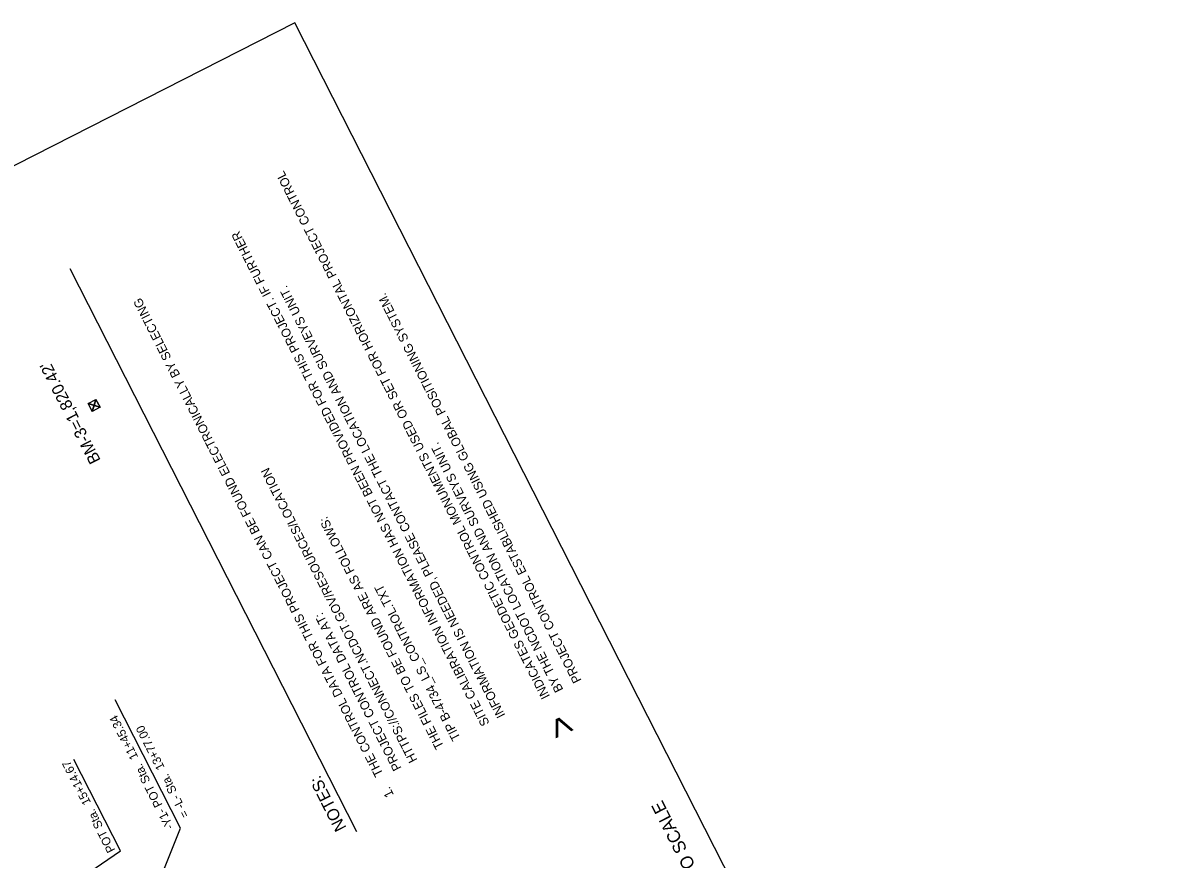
# Model space of a CAD drawing. Extents: x 558500 to 560321, y 514546 to 516470.
# Drawn here: x 559286 to 560218, y 515787 to 516470 of the extents above; entities that cross this region are included whole.
import ezdxf

# ---------------------------------------------------------------- set-up
doc = ezdxf.new("R2010")
doc.units = 0
for name, color, linetype in [('CTL Bench Mark CELL', 7, 'Continuous'), ('CTL Sheet Border CELL', 7, 'Continuous'), ('CTL Sheet Notes CELL', 7, 'Continuous'), ('CTL Supplemental Horizontal and Vertical Text', 7, 'Continuous'), ('Prop Horizontal Alignment Station Label', 7, 'Continuous')]:
    doc.layers.add(name, color=color, linetype=linetype)

msp = doc.modelspace()

# ---------------------------------------------------------------- linework, layer by layer
at = {"layer": 'CTL Bench Mark CELL'}
msp.add_line((559344.09, 516157.75), (559344.09, 516157.75), dxfattribs=at)
msp.add_lwpolyline([(559345.57, 516162.62), (559348.94, 516156.27), (559342.59, 516152.9), (559339.22, 516159.25)], close=True, dxfattribs=at)
for points in [[(559348.94, 516156.27), (559339.22, 516159.25), (559344.08, 516157.76), (559342.59, 516152.9), (559345.57, 516162.62)], [(559344.08, 516157.76), (559339.22, 516159.25), (559342.59, 516152.9), (559344.08, 516157.76)], [(559344.08, 516157.76), (559348.94, 516156.27), (559345.57, 516162.62), (559344.08, 516157.76)]]:
    msp.add_lwpolyline(points, dxfattribs=at)
at = {"layer": 'CTL Sheet Border CELL'}
for p, q in [((559508.09, 516470.33), (558531.71, 515973.23)), ((560218.25, 515075.49), (559508.09, 516470.33))]:
    msp.add_line(p, q, dxfattribs=at)
at = {"layer": 'CTL Sheet Notes CELL'}
msp.add_line((559558.64, 515809.53), (559324.68, 516269.42), dxfattribs=at)
at = {"layer": 'Prop Horizontal Alignment Station Label'}
for p, q in [((559414.66, 515812.44), (559361.24, 515917.36)), ((559365.63, 515793.86), (559327.55, 515868.65)), ((559365.53, 515689.77), (559414.66, 515812.44)), ((559265.98, 515725.85), (559365.63, 515793.86))]:
    msp.add_line(p, q, dxfattribs=at)

# ---------------------------------------------------------------- texts
at = {"layer": 'CTL Sheet Border CELL'}
msp.add_text('NOTE: DRAWING NOT TO SCALE', height=10.4348, rotation=116.87668, dxfattribs=at).set_placement((559907.7, 515639.52))
at = {"layer": 'CTL Sheet Notes CELL'}
for s, height, rotation, p in [('INDICATES GEODETIC CONTROL MONUMENTS USED OR SET FOR HORIZONTAL PROJECT CONTROL', 7.337, 116.85803, (559716.63, 515920.14)), ('SITE CALIBRATION INFORMATION HAS NOT BEEN PROVIDED FOR THIS PROJECT. IF FURTHER', 7.337, 116.96328, (559667.33, 515898.11)), ('INFORMATION IS NEEDED, PLEASE CONTACT THE LOCATION AND SURVEYS UNIT.', 7.337, 116.96328, (559680.21, 515904.66)), ('PROJECT CONTROL ESTABLISHED USING GLOBAL POSITIONING SYSTEM.', 7.337, 116.85803, (559742.41, 515933.19)), ('1.    THE CONTROL DATA FOR THIS PROJECT CAN BE FOUND ELECTRONICALLY BY SELECTING', 7.337, 116.96328, (559589.14, 515839.68)), ('BY THE NCDOT LOCATION AND SURVEYS UNIT.', 7.337, 116.85803, (559727.54, 515925.63)), ('HTTPS://CONNECT.NCDOT.GOV/RESOURCES/LOCATION', 7.337, 116.96328, (559608.4, 515868.13)), ('THE FILES TO BE FOUND ARE AS FOLLOWS:', 7.337, 116.96328, (559630.01, 515879.12)), ('TIP B-4734_LS_CONTROL.TXT', 7.337, 116.96328, (559643.59, 515886.03)), ('PROJECT CONTROL DATA AT:', 7.337, 116.96328, (559595.44, 515861.53)), ('>', 21.9, 114.92026, (559738.71, 515892.34)), ('NOTES:', 9.783, 116.85803, (559550.41, 515812.82))]:
    msp.add_text(s, height=height, rotation=rotation, dxfattribs=at).set_placement(p)
at = {"layer": 'CTL Supplemental Horizontal and Vertical Text'}
msp.add_text("BM-3=1,820.42'", height=9.7178, rotation=117.15351, dxfattribs=at).set_placement((559349.76, 516113.05))
at = {"layer": 'Prop Horizontal Alignment Station Label'}
for s, p in [('-Y1- POT Sta.  11+45.34', (559409.39, 515813.45)), ('= -L- Sta.  13+77.00', (559421.9, 515822.97)), ('POT Sta.  15+14.67', (559361.52, 515794.55))]:
    msp.add_text(s, height=7, rotation=116.98193, dxfattribs=at).set_placement(p)

doc.saveas('drawing.dxf')
